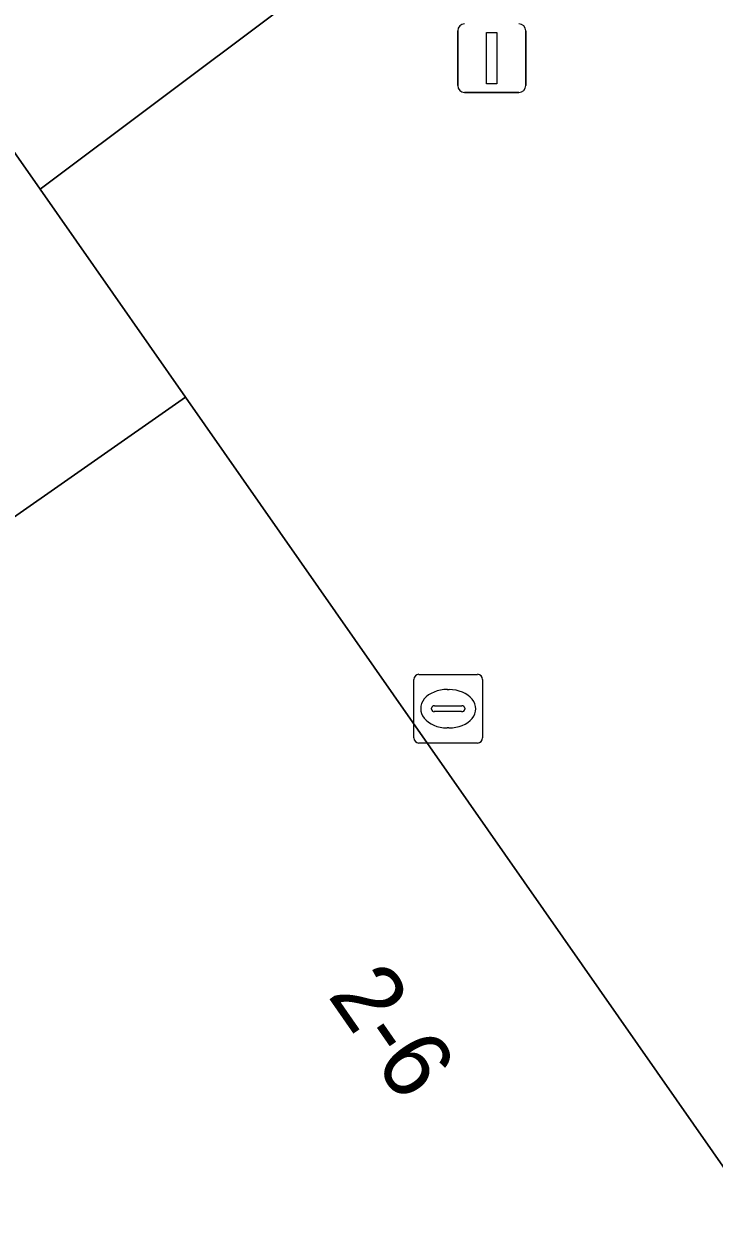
# Model space of a CAD drawing. Extents: x 161087 to 161926, y 382572 to 383873.
# Drawn here: x 161410.1 to 161420.15, y 383042.41 to 383059.77 of the extents above; entities that cross this region are included whole.
import ezdxf

# ---------------------------------------------------------------- set-up
doc = ezdxf.new("R2010")
doc.units = 0
for name, color, linetype in [('IMGEO_Lichtmast', 7, 'Continuous'), ('IMGEO_Pand', 7, 'Continuous'), ('IMGEO_Pand_nummerreeks', 7, 'Continuous'), ('IMGEO_Rioolput', 7, 'Continuous'), ('IMGEO_Voetgangersgebied_open', 7, 'Continuous')]:
    doc.layers.add(name, color=color, linetype=linetype)

msp = doc.modelspace()

# ---------------------------------------------------------------- linework, layer by layer
at = {"layer": 'IMGEO_Lichtmast'}
for p, q in [((161416.417, 383058.866), (161416.417, 383059.666)), ((161416.417, 383059.666), (161416.417, 383058.866)), ((161417.407, 383059.666), (161417.407, 383058.866)), ((161417.407, 383058.866), (161417.407, 383059.666)), ((161417.307, 383058.766), (161416.517, 383058.766)), ((161416.517, 383058.766), (161417.307, 383058.766))]:
    msp.add_line(p, q, dxfattribs=at)
msp.add_lwpolyline([(161416.837, 383059.641), (161416.987, 383059.641), (161416.987, 383058.891), (161416.837, 383058.891), (161416.837, 383059.641)], dxfattribs=at)
for centre, start, end in [((161416.517, 383059.666), 90, 180), ((161416.517, 383059.666), 90, 180), ((161417.307, 383059.666), 0, 90), ((161417.307, 383059.666), 360, 90), ((161416.517, 383058.866), 180, 270), ((161416.517, 383058.866), 180, 270), ((161417.307, 383058.866), 270, 0), ((161417.307, 383058.866), 270, 0)]:
    msp.add_arc(centre, 0.1, start, end, dxfattribs=at)
at = {"layer": 'IMGEO_Pand'}
for points in [[(161412.451, 383054.33), (161410.333, 383057.358), (161409.317, 383058.811), (161403.938, 383055.073), (161401.472, 383053.348), (161398.363, 383057.796), (161393.488, 383054.156), (161396.615, 383049.94), (161395.036, 383048.836), (161398.174, 383044.348)], [(161412.451, 383054.33), (161398.174, 383044.348), (161409.862, 383027.631), (161412.727, 383023.533), (161427.003, 383033.515)]]:
    msp.add_lwpolyline(points, close=True, dxfattribs=at)
at = {"layer": 'IMGEO_Rioolput'}
for p, q in [((161415.777, 383049.368), (161415.777, 383050.22)), ((161415.852, 383050.294), (161416.704, 383050.294)), ((161416.778, 383050.22), (161416.778, 383049.368)), ((161416.265, 383050.074), (161416.29, 383050.074)), ((161416.036, 383049.788), (161416.036, 383049.8)), ((161416.474, 383049.751), (161416.076, 383049.751)), ((161416.079, 383049.837), (161416.477, 383049.837)), ((161416.52, 383049.8), (161416.52, 383049.788)), ((161416.288, 383049.514), (161416.263, 383049.514)), ((161416.704, 383049.294), (161415.852, 383049.294))]:
    msp.add_line(p, q, dxfattribs=at)
for points in [[(161415.777, 383049.368), (161415.777, 383050.22)], [(161415.852, 383050.294), (161416.704, 383050.294)], [(161416.778, 383050.22), (161416.778, 383049.368)], [(161416.704, 383049.294), (161415.852, 383049.294)]]:
    msp.add_lwpolyline(points, dxfattribs=at)
for centre, radius, start, end in [((161415.854, 383050.218), 0.0765, 91.552, 178.448), ((161415.854, 383050.218), 0.0765, 91.552, 178.448), ((161416.702, 383050.218), 0.0765, 1.552, 88.448), ((161416.702, 383050.218), 0.0765, 1.552, 88.448), ((161416.076, 383049.797), 0.0403, 85.8775, 175.7526), ((161416.073, 383049.787), 0.0366, 178.938, 274.7102), ((161416.477, 383049.794), 0.043, 264.8664, 352.4533), ((161416.481, 383049.799), 0.0386, 1.7309, 96.639), ((161415.854, 383049.37), 0.0765, 181.552, 268.448), ((161415.854, 383049.37), 0.0765, 181.552, 268.448), ((161416.702, 383049.37), 0.0765, 271.552, 358.448), ((161416.702, 383049.37), 0.0765, 271.552, 358.448)]:
    msp.add_arc(centre, radius, start, end, dxfattribs=at)
for centre, major_axis, ratio, start_param, end_param in [((161416.264, 383049.794), (-0.387, 0.002), 0.722429, 4.712389, 7.853982), ((161416.289, 383049.794), (-0.39, 0.002), 0.717154, 1.570796, 4.712389)]:
    msp.add_ellipse(centre, major_axis=major_axis, ratio=ratio, start_param=start_param, end_param=end_param, dxfattribs=at)
at = {"layer": 'IMGEO_Voetgangersgebied_open'}
msp.add_lwpolyline([(161412.931, 383076.866), (161412.187, 383076.309), (161412.019, 383076.533), (161409.689, 383074.789), (161409.821, 383074.613), (161409.461, 383074.343), (161409.599, 383074.159), (161407.725, 383072.757), (161407.588, 383072.941), (161407.512, 383072.884), (161408.505, 383071.545), (161408.876, 383071.82), (161409.745, 383070.662), (161406.572, 383068.175), (161408.611, 383065.45), (161399.459, 383058.615), (161400.886, 383056.575), (161402.23, 383057.515), (161403.938, 383055.073), (161409.317, 383058.811), (161410.333, 383057.358), (161432.896, 383074.264), (161436.953, 383077.304)], dxfattribs=at)
msp.add_lwpolyline([(161436.953, 383077.304), (161432.896, 383074.264), (161410.333, 383057.358), (161412.451, 383054.33), (161427.003, 383033.515), (161429.943, 383029.064), (161430.511, 383028.577), (161432.084, 383029.67), (161452.689, 383000), (161453.475, 382998.869), (161463.693, 383005.964), (161466.917, 383001.359), (161482.447, 383012.169)], close=True, dxfattribs=at)

# ---------------------------------------------------------------- texts
at = {"layer": 'IMGEO_Pand_nummerreeks'}
msp.add_text('2-6', height=1, rotation=304.7981, dxfattribs=at).set_placement((161414.511, 383045.619))

doc.saveas('drawing.dxf')
